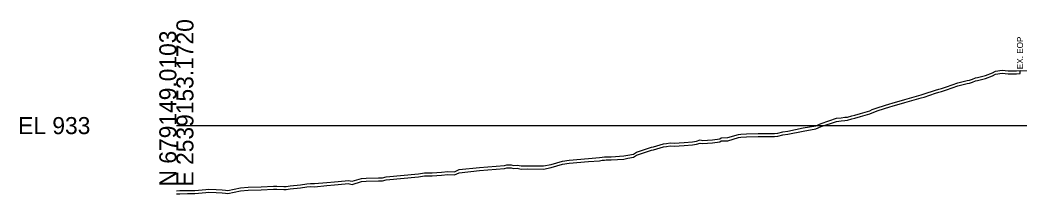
# Model space of a CAD drawing. Extents: x -26 to 2539581, y -16 to 679563.
# Drawn here: x -25.7 to 138.6, y 4488.8 to 4517.3 of the extents above; entities that cross this region are included whole.
import ezdxf

# ---------------------------------------------------------------- set-up
doc = ezdxf.new("R2010")
doc.units = 0
for name, color, linetype in [('DESIGN - SHEET - Light Grid', 7, 'Continuous'), ('SURVEY - GROUND - Bottom of Topsoil Layer', 7, 'Continuous'), ('SURVEY - GROUND - Existing Pavement Text', 7, 'Continuous'), ('SURVEY - GROUND - Top of Ground', 7, 'Continuous')]:
    doc.layers.add(name, color=color, linetype=linetype)

msp = doc.modelspace()

# ---------------------------------------------------------------- linework, layer by layer
at = {"layer": 'DESIGN - SHEET - Light Grid'}
msp.add_line((0, 4500), (150, 4500), dxfattribs=at)
at = {"layer": 'SURVEY - GROUND - Bottom of Topsoil Layer'}
for p, q in [((134.1, 4508.16), (134.58, 4508.46)), ((134.58, 4508.46), (135.69, 4508.62)), ((135.69, 4508.62), (136.67, 4508.5)), ((136.67, 4508.5), (137.35, 4508.51)), ((137.35, 4508.51), (138.05, 4508.48)), ((138.05, 4508.48), (138.6, 4508.56)), ((138.6, 4508.56), (138.6, 4509.06)), ((138.6, 4508.56), (138.6, 4508.56)), ((128.36, 4506.54), (129.92, 4506.92)), ((129.92, 4506.92), (130.29, 4506.95)), ((130.29, 4506.95), (130.81, 4507.13)), ((130.81, 4507.13), (131.27, 4507.36)), ((131.27, 4507.36), (131.6, 4507.39)), ((131.6, 4507.39), (132.94, 4507.73)), ((132.94, 4507.73), (134.1, 4508.16)), ((122.87, 4504.69), (124.69, 4505.3)), ((124.69, 4505.3), (125.29, 4505.48)), ((125.29, 4505.48), (125.71, 4505.6)), ((125.71, 4505.6), (126.5, 4505.88)), ((126.5, 4505.88), (128.36, 4506.54)), ((117.6, 4503.18), (119.66, 4503.78)), ((119.66, 4503.78), (122.35, 4504.57)), ((122.35, 4504.57), (122.87, 4504.69)), ((112.41, 4501.5), (113.93, 4501.95)), ((113.93, 4501.95), (114.33, 4502.12)), ((114.33, 4502.12), (115.28, 4502.47)), ((115.28, 4502.47), (117.22, 4503.07)), ((117.22, 4503.07), (117.6, 4503.18)), ((105.94, 4499.84), (108.46, 4500.7)), ((108.46, 4500.7), (109.21, 4500.77)), ((109.21, 4500.77), (109.8, 4500.86)), ((109.8, 4500.86), (110.27, 4500.88)), ((110.27, 4500.88), (110.95, 4501.09)), ((110.95, 4501.09), (111.47, 4501.22)), ((111.47, 4501.22), (112.41, 4501.5)), ((98.82, 4498.27), (99.64, 4498.49)), ((99.64, 4498.49), (100.47, 4498.57)), ((100.47, 4498.57), (102.99, 4499.11)), ((102.99, 4499.11), (105.05, 4499.47)), ((105.05, 4499.47), (105.94, 4499.84)), ((81.79, 4496.64), (83.45, 4496.72)), ((83.45, 4496.72), (84.82, 4496.84)), ((84.82, 4496.84), (85.47, 4496.94)), ((85.47, 4496.94), (86.07, 4497.14)), ((86.07, 4497.14), (86.44, 4497.06)), ((86.44, 4497.06), (88.1, 4497.18)), ((88.1, 4497.18), (89.31, 4497.31)), ((89.31, 4497.31), (89.52, 4497.48)), ((89.52, 4497.48), (90.59, 4497.52)), ((90.59, 4497.52), (92.37, 4498.02)), ((92.37, 4498.02), (92.74, 4498.1)), ((92.74, 4498.1), (93.65, 4498.14)), ((93.65, 4498.14), (95.6, 4498.19)), ((95.6, 4498.19), (97, 4498.2)), ((97, 4498.2), (98.26, 4498.22)), ((98.26, 4498.22), (98.82, 4498.27)), ((75.11, 4494.83), (75.6, 4495.14)), ((75.6, 4495.14), (78.06, 4495.96)), ((78.06, 4495.96), (78.36, 4496.04)), ((78.36, 4496.04), (80.04, 4496.53)), ((80.04, 4496.53), (80.51, 4496.56)), ((80.51, 4496.56), (81.1, 4496.67)), ((81.1, 4496.67), (81.79, 4496.64)), ((61.58, 4493.1), (63.42, 4493.65)), ((63.42, 4493.65), (64.52, 4493.83)), ((64.52, 4493.83), (67.7, 4494.08)), ((67.7, 4494.08), (69.49, 4494.24)), ((69.49, 4494.24), (69.93, 4494.32)), ((69.93, 4494.32), (70.32, 4494.35)), ((70.32, 4494.35), (70.63, 4494.38)), ((70.63, 4494.38), (71.41, 4494.37)), ((71.41, 4494.37), (73.51, 4494.51)), ((73.51, 4494.51), (74.16, 4494.64)), ((74.16, 4494.64), (75.11, 4494.83)), ((42.04, 4491.75), (43.54, 4491.86)), ((43.54, 4491.86), (44.58, 4491.96)), ((44.58, 4491.96), (45.68, 4491.91)), ((45.68, 4491.91), (46.48, 4492.27)), ((46.48, 4492.27), (49.8, 4492.62)), ((49.8, 4492.62), (53.91, 4492.94)), ((53.91, 4492.94), (54.28, 4493.05)), ((54.28, 4493.05), (54.99, 4493.07)), ((54.99, 4493.07), (55.38, 4492.95)), ((55.38, 4492.95), (55.99, 4493.02)), ((55.99, 4493.02), (56.63, 4492.87)), ((56.63, 4492.87), (57.69, 4492.88)), ((57.69, 4492.88), (60.3, 4492.87)), ((60.3, 4492.87), (61.58, 4493.1)), ((22.68, 4489.97), (24.71, 4490.18)), ((24.71, 4490.18), (25.98, 4490.26)), ((25.98, 4490.26), (27.71, 4490.43)), ((27.71, 4490.43), (28.2, 4490.48)), ((28.2, 4490.48), (28.88, 4490.35)), ((28.88, 4490.35), (30.44, 4490.8)), ((30.44, 4490.8), (31.17, 4490.89)), ((31.17, 4490.89), (33.19, 4490.94)), ((33.19, 4490.94), (33.89, 4490.93)), ((33.89, 4490.93), (34.46, 4491.08)), ((34.46, 4491.08), (39.76, 4491.59)), ((39.76, 4491.59), (40.74, 4491.73)), ((40.74, 4491.73), (42.04, 4491.75)), ((0, 4488.77), (0.56, 4488.82)), ((0.56, 4488.82), (1.84, 4488.83)), ((1.84, 4488.83), (3.05, 4488.87)), ((3.05, 4488.87), (4.83, 4489.03)), ((4.83, 4489.03), (5.3, 4489.07)), ((5.3, 4489.07), (6.55, 4489.01)), ((6.55, 4489.01), (7.51, 4488.97)), ((7.51, 4488.97), (8.05, 4488.88)), ((8.05, 4488.88), (8.47, 4488.84)), ((8.47, 4488.84), (10.55, 4489.28)), ((10.55, 4489.28), (11.79, 4489.4)), ((11.79, 4489.4), (13.95, 4489.44)), ((13.95, 4489.44), (15.98, 4489.58)), ((15.98, 4489.58), (16.53, 4489.58)), ((16.53, 4489.58), (17.67, 4489.51)), ((17.67, 4489.51), (18.01, 4489.5)), ((18.01, 4489.5), (18.68, 4489.62)), ((18.68, 4489.62), (20.37, 4489.79)), ((20.37, 4489.79), (21.45, 4489.93)), ((21.45, 4489.93), (22.06, 4489.99)), ((22.06, 4489.99), (22.68, 4489.97))]:
    msp.add_line(p, q, dxfattribs=at)
at = {"layer": 'SURVEY - GROUND - Top of Ground'}
msp.add_lwpolyline([(0, 4489.27), (0.56, 4489.32), (1.84, 4489.33), (3.05, 4489.37), (4.83, 4489.53), (5.3, 4489.57), (6.55, 4489.51), (7.51, 4489.47), (8.05, 4489.38), (8.47, 4489.34), (10.55, 4489.78), (11.79, 4489.9), (13.95, 4489.94), (15.98, 4490.08), (16.53, 4490.08), (17.67, 4490.01), (18.01, 4490), (18.68, 4490.12), (20.37, 4490.29), (21.45, 4490.43), (22.06, 4490.49), (22.68, 4490.47), (24.71, 4490.68), (25.98, 4490.76), (27.71, 4490.93), (28.2, 4490.98), (28.88, 4490.85), (30.44, 4491.3), (31.17, 4491.39), (33.19, 4491.44), (33.89, 4491.43), (34.46, 4491.58), (39.76, 4492.09), (40.74, 4492.23), (42.04, 4492.25), (43.54, 4492.36), (44.58, 4492.46), (45.68, 4492.41), (46.48, 4492.77), (49.8, 4493.12), (53.91, 4493.44), (54.28, 4493.55), (54.99, 4493.57), (55.38, 4493.45), (55.99, 4493.52), (56.63, 4493.37), (57.69, 4493.38), (60.3, 4493.37), (61.58, 4493.6), (63.42, 4494.15), (64.52, 4494.33), (67.7, 4494.58), (69.49, 4494.74), (69.93, 4494.82), (70.32, 4494.85), (70.63, 4494.88), (71.41, 4494.87), (73.51, 4495.01), (74.16, 4495.14), (75.11, 4495.33), (75.6, 4495.64), (78.06, 4496.46), (78.36, 4496.54), (80.04, 4497.03), (80.51, 4497.06), (81.1, 4497.17), (81.79, 4497.14), (83.45, 4497.22), (84.82, 4497.34), (85.47, 4497.44), (86.07, 4497.64), (86.44, 4497.56), (88.1, 4497.68), (89.31, 4497.81), (89.52, 4497.98), (90.59, 4498.02), (92.37, 4498.52), (92.74, 4498.6), (93.65, 4498.64), (95.6, 4498.69), (97, 4498.7), (98.26, 4498.72), (98.82, 4498.77), (99.64, 4498.99), (100.47, 4499.07), (102.99, 4499.61), (105.05, 4499.97), (105.94, 4500.34), (108.46, 4501.2), (109.21, 4501.27), (109.8, 4501.36), (110.27, 4501.38), (110.95, 4501.59), (111.47, 4501.72), (112.41, 4502), (113.93, 4502.45), (114.33, 4502.62), (115.28, 4502.97), (117.22, 4503.57), (117.6, 4503.68), (119.66, 4504.28), (122.35, 4505.07), (122.87, 4505.19), (124.69, 4505.8), (125.29, 4505.98), (125.71, 4506.1), (126.5, 4506.38), (128.36, 4507.04), (129.92, 4507.42), (130.29, 4507.45), (130.81, 4507.63), (131.27, 4507.86), (131.6, 4507.89), (132.94, 4508.23), (134.1, 4508.66), (134.58, 4508.96), (135.69, 4509.12), (136.67, 4509), (137.35, 4509.01), (138.05, 4508.98), (138.6, 4509.06), (141.21, 4508.99)], dxfattribs=at)

# ---------------------------------------------------------------- texts
at = {"layer": 'DESIGN - SHEET - Light Grid'}
for s, p in [('E 2539153.1720', (2.8, 4490)), ('N 679149.0103', (0, 4490))]:
    msp.add_text(s, height=2.8, rotation=90, dxfattribs=at).set_placement(p)
msp.add_text('EL 933', height=2.8, dxfattribs=at).set_placement((-26, 4498.6))
at = {"layer": 'SURVEY - GROUND - Existing Pavement Text'}
msp.add_text('EX. EOP', height=1, rotation=90, dxfattribs=at).set_placement((139.1, 4509.26))

doc.saveas('drawing.dxf')
